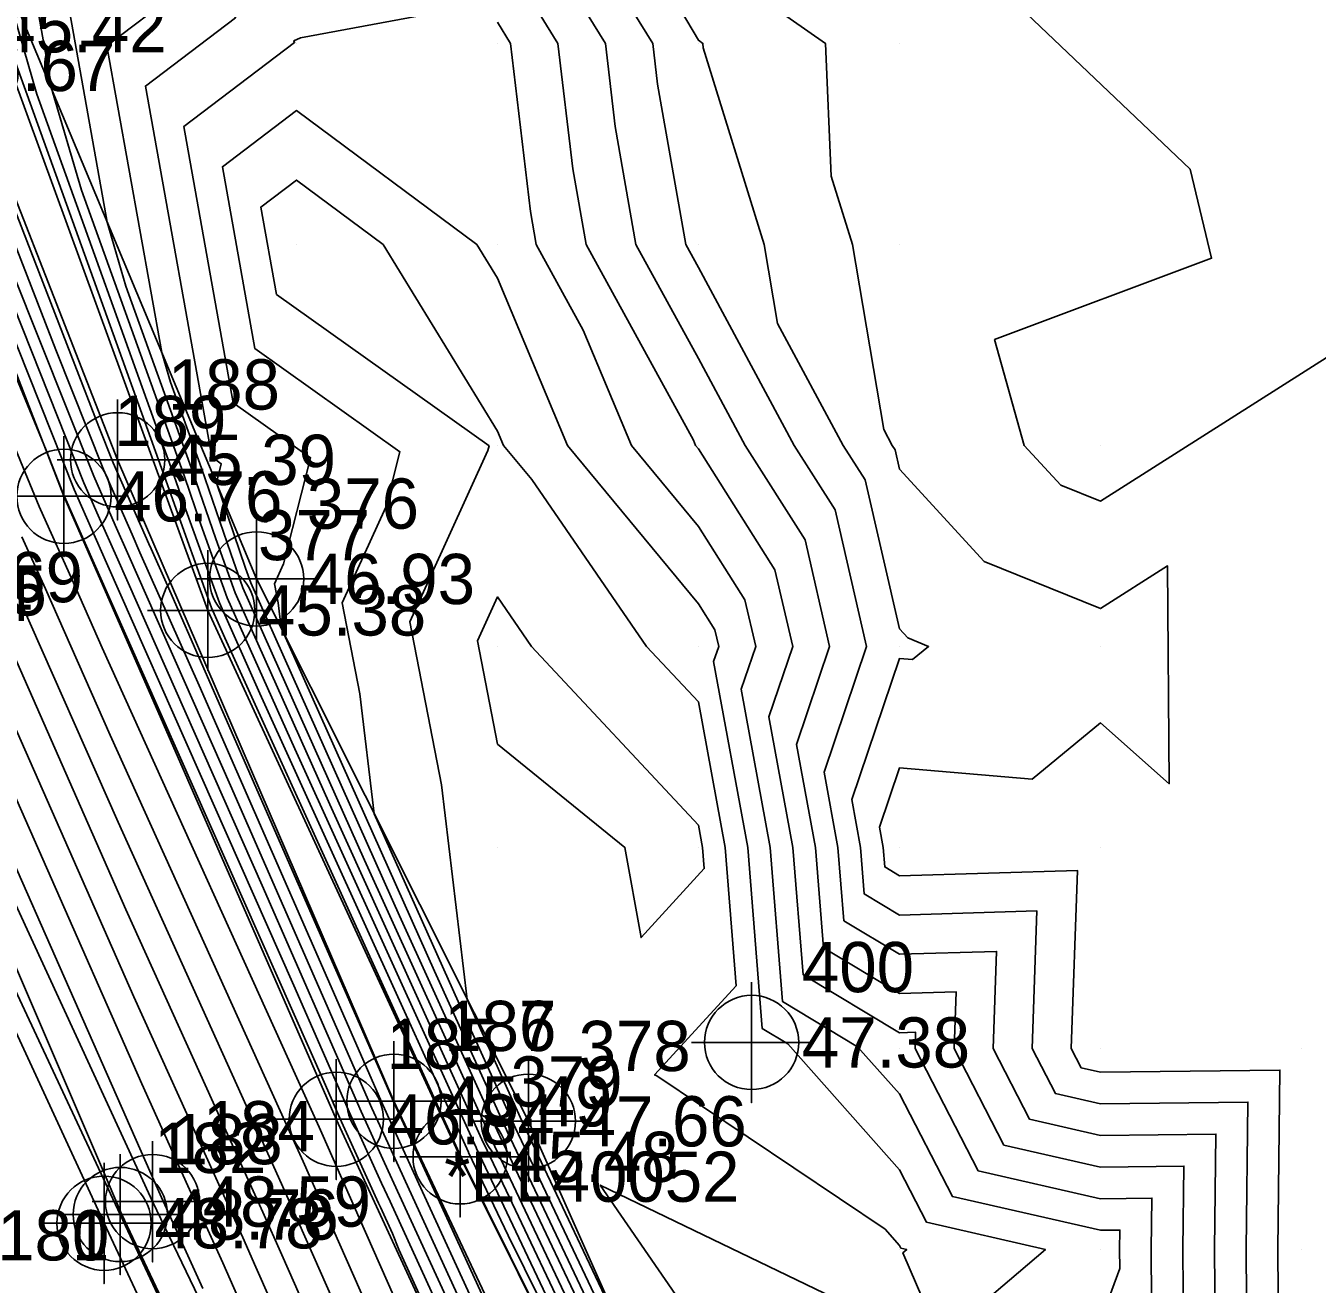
# Model space of a CAD drawing. Extents: x 2090860 to 2091277, y 159470 to 160080.
# Drawn here: x 2091106.5 to 2091170.8, y 159678.3 to 159740.9 of the extents above; entities that cross this region are included whole.
import ezdxf

# ---------------------------------------------------------------- set-up
doc = ezdxf.new("R2010")
doc.units = 0
for name, color, linetype in [('DTM Contours Major', 7, 'Continuous'), ('DTM Contours Minor', 7, 'Continuous'), ('Exist DTM Breakline', 7, 'Continuous'), ('Exist DTM Breakline Cogo Comment', 7, 'Continuous'), ('Exist DTM Breakline Cogo Elevation', 7, 'Continuous'), ('Exist DTM Breakline Cogo Number', 7, 'Continuous'), ('Exist DTM Breakline Cogo Point CELL', 7, 'Continuous'), ('Exist DTM Crownline Cogo Number', 7, 'Continuous'), ('Exist DTM QL2 LIDAR Elevation Point', 7, 'Continuous'), ('Exist DTM Regular Point CELL', 7, 'Continuous'), ('Exist DTM Regular Point Cogo Elevation', 7, 'Continuous'), ('Exist DTM Regular Point Cogo Number', 7, 'Continuous'), ('Exist Roads EOP', 7, 'Continuous'), ('Exist Roads EOP Cogo Elevation', 7, 'Continuous'), ('Exist Roads EOP Cogo Number', 7, 'Continuous'), ('Exist Roads EOP Cogo Point CELL', 7, 'Continuous'), ('Exist Roads EOT', 7, 'Continuous'), ('Exist Roads EOT Cogo Elevation', 7, 'Continuous'), ('Exist Roads EOT Cogo Number', 7, 'Continuous'), ('Exist Roads EOT Cogo Point CELL', 7, 'Continuous')]:
    doc.layers.add(name, color=color, linetype=linetype)

msp = doc.modelspace()

# ---------------------------------------------------------------- linework, layer by layer
at = {"layer": 'DTM Contours Major'}
for points in [[(2091113.978, 159781.196), (2091107.95, 159774.542), (2091109.45, 159770.226), (2091108.284, 159761.501), (2091106.966, 159748.316), (2091108.177, 159744.971), (2091106.747, 159743.886), (2091107.873, 159737.592), (2091109.304, 159732.696), (2091114.431, 159718.45), (2091115.247, 159716.067), (2091116.563, 159712.414), (2091119.92, 159704.896), (2091128.935, 159685.065), (2091128.953, 159685.024), (2091132.725, 159677.067), (2091142.133, 159658.086), (2091142.373, 159657.575), (2091143.105, 159656.097), (2091147.178, 159648.664), (2091157.027, 159629.517), (2091160.822, 159622.14), (2091162.224, 159619.585), (2091172.872, 159598.824)], [(2091167.296, 159672.704), (2091167.247, 159680), (2091167.328, 159687.328), (2091160, 159687.24), (2091157.753, 159687.753), (2091156.595, 159690), (2091156.838, 159696.838), (2091150, 159696.631), (2091148.246, 159697.686), (2091148.062, 159700), (2091147.627, 159702.373), (2091150, 159709.403), (2091150.652, 159709.348), (2091151.447, 159710), (2091150.417, 159710.417), (2091150, 159710.871), (2091148.285, 159718.285), (2091147.2, 159720), (2091143.935, 159726.065), (2091143.272, 159730), (2091140.232, 159739.768), (2091140.222, 159740), (2091140, 159740.155), (2091134.169, 159750)], [(2091126.87, 159693.834), (2091119.241, 159710.914), (2091119.091, 159712.158), (2091118.907, 159713.104), (2091119.361, 159714.098), (2091120.706, 159719.383), (2091116.861, 159722.121), (2091114.403, 159735.865), (2091119.906, 159740.039), (2091119.875, 159740.125), (2091120.209, 159740.28), (2091128.27, 159741.774)], [(2091130, 159741.057), (2091130.655, 159740), (2091131.642, 159731.642), (2091131.931, 159730), (2091134.269, 159725.731), (2091136.668, 159720), (2091140, 159715.97), (2091142.312, 159712.312), (2091142.847, 159710), (2091142.129, 159707.871), (2091143.571, 159700), (2091144.184, 159692.326), (2091147.91, 159690.084), (2091150, 159687.733), (2091152.629, 159682.629), (2091160, 159680.949), (2091160.96, 159680.96), (2091160.95, 159680), (2091160.956, 159679.044), (2091160, 159676.442)], [(2091133.499, 159658.093), (2091123.124, 159681.571), (2091121.327, 159685.637), (2091121.124, 159686.085), (2091110.337, 159709.925), (2091108.79, 159713.43), (2091107.412, 159716.477), (2091107.198, 159716.962), (2091099.863, 159734.767)], [(2091132.508, 159667.94), (2091125.612, 159682.971), (2091124.541, 159685.304), (2091123.76, 159687.025), (2091116.729, 159703.079), (2091111.667, 159714.499), (2091110.986, 159716.037), (2091109.918, 159718.472), (2091105.9, 159728.566)], [(2091121.742, 159670.624), (2091117.989, 159679.115), (2091117.339, 159680.586), (2091115.905, 159683.748), (2091111.915, 159692.566), (2091103.71, 159711.156)], [(2091172.606, 159609.793), (2091167.266, 159614.052), (2091165.877, 159617.077), (2091164.245, 159620.259), (2091159.237, 159629.383), (2091158.623, 159630.578), (2091157.028, 159633.678), (2091144.289, 159656.927), (2091144.155, 159657.198), (2091143.409, 159658.787), (2091141.517, 159662.605), (2091130.506, 159685.833), (2091130.452, 159685.953), (2091126.87, 159693.834)]]:
    msp.add_lwpolyline(points, dxfattribs=at)
at = {"layer": 'DTM Contours Minor'}
for points in [[(2091104.981, 159783.106), (2091105.494, 159775.383), (2091105.019, 159773.619), (2091104.746, 159770.703), (2091102.113, 159749.038), (2091103.646, 159746.449), (2091104.874, 159742.247), (2091113.588, 159718.033), (2091113.763, 159717.52), (2091115.783, 159711.911), (2091116.446, 159710.426), (2091128.176, 159684.621), (2091128.177, 159684.619), (2091128.329, 159684.298), (2091134.074, 159672.707)], [(2091113.452, 159782.082), (2091106.971, 159774.929), (2091107.612, 159773.082), (2091107.114, 159769.349), (2091104.896, 159747.166), (2091105.245, 159746.204), (2091104.833, 159745.892), (2091105.157, 159744.081), (2091107.089, 159737.471), (2091114.009, 159718.241), (2091114.505, 159716.794), (2091116.173, 159712.162), (2091118.183, 159707.661), (2091128.555, 159684.843), (2091128.565, 159684.821), (2091130.527, 159680.683), (2091141.814, 159657.91), (2091141.927, 159657.669), (2091142.809, 159655.89), (2091144.716, 159652.41), (2091156.628, 159629.252), (2091161.218, 159620.33), (2091161.719, 159619.417), (2091174.621, 159594.26)], [(2091122.861, 159781.908), (2091128.215, 159769.149), (2091125.426, 159758.204), (2091124.754, 159757.835), (2091125.475, 159756.447), (2091126.274, 159756.566), (2091136.123, 159756.123), (2091139.218, 159750), (2091140, 159748.68), (2091144.395, 159745.605), (2091153.611, 159744.078), (2091164.457, 159733.742), (2091165.521, 159729.312), (2091154.731, 159725.269), (2091156.202, 159720), (2091158.019, 159718.019), (2091160, 159717.218), (2091172.816, 159725.36)], [(2091122.375, 159778.639), (2091115.032, 159779.423), (2091109.908, 159773.768), (2091113.125, 159764.514), (2091111.434, 159751.856), (2091114.026, 159748.824), (2091112.082, 159747.918), (2091114.042, 159742.505), (2091110.575, 159739.876), (2091113.305, 159724.616), (2091113.735, 159723.145), (2091115.274, 159718.867), (2091116.731, 159714.614), (2091117.342, 159712.916), (2091123.395, 159699.365), (2091129.693, 159685.509), (2091129.729, 159685.429), (2091137.121, 159669.836)], [(2091122.253, 159777.822), (2091115.559, 159778.537), (2091110.888, 159773.381), (2091114.962, 159761.657), (2091114.117, 159755.328), (2091121.559, 159746.623), (2091115.979, 159744.021), (2091116.974, 159741.272), (2091112.489, 159737.87), (2091115.788, 159719.427), (2091116.265, 159719.088), (2091116.021, 159718.127), (2091117.473, 159713.888), (2091117.732, 159713.168), (2091125.132, 159696.599), (2091130.073, 159685.731), (2091130.118, 159685.631), (2091139.319, 159666.221)], [(2091164.126, 159675.874), (2091164.098, 159680), (2091164.144, 159684.144), (2091160, 159684.095), (2091155.191, 159685.191), (2091152.714, 159690), (2091152.814, 159692.814), (2091150, 159692.728), (2091146.215, 159695.006), (2091145.816, 159700), (2091144.878, 159705.122), (2091146.524, 159710), (2091145.299, 159715.299), (2091142.326, 159720), (2091140, 159724.32), (2091136.889, 159730), (2091135.859, 159735.859), (2091135.37, 159740), (2091130, 159748.673)], [(2091134.034, 159745.966), (2091137.728, 159740), (2091137.968, 159737.968), (2091139.368, 159730), (2091140, 159728.847), (2091144.763, 159720), (2091146.792, 159716.792), (2091148.363, 159710), (2091146.252, 159703.748), (2091146.939, 159700), (2091147.231, 159696.346), (2091150, 159694.68), (2091154.826, 159694.826), (2091154.655, 159690), (2091156.472, 159686.472), (2091160, 159685.668), (2091165.736, 159685.736), (2091165.673, 159680), (2091165.711, 159674.289)], [(2091162.541, 159677.459), (2091162.524, 159680), (2091162.552, 159682.552), (2091160, 159682.522), (2091153.91, 159683.91), (2091150.773, 159690), (2091150.802, 159690.802), (2091150, 159690.777), (2091145.2, 159693.666), (2091144.694, 159700), (2091143.503, 159706.497), (2091144.686, 159710), (2091143.806, 159713.806), (2091140, 159719.824), (2091139.855, 159720), (2091139.75, 159720.25), (2091134.41, 159730), (2091133.751, 159733.751), (2091133.012, 159740), (2091130, 159744.865)], [(2091168.882, 159671.118), (2091168.821, 159680), (2091168.92, 159688.92), (2091160, 159688.813), (2091159.034, 159689.034), (2091158.536, 159690), (2091158.85, 159698.85), (2091150, 159698.582), (2091149.262, 159699.026), (2091149.184, 159700), (2091149.001, 159700.999), (2091150, 159703.958), (2091156.6, 159703.4), (2091160, 159706.189), (2091163.416, 159703.168), (2091163.337, 159713.999), (2091160, 159711.879), (2091154.218, 159714.218), (2091150, 159718.818), (2091149.778, 159719.778), (2091149.637, 159720), (2091149.214, 159720.786), (2091147.664, 159730), (2091146.608, 159733.392), (2091146.313, 159740), (2091140, 159744.418)], [(2091113.443, 159677.236), (2091111.307, 159681.76), (2091110.309, 159684.106), (2091099.498, 159709.302), (2091098.524, 159711.61), (2091097.844, 159713.197), (2091091.534, 159728.707), (2091087.955, 159732.339), (2091087.995, 159731.685), (2091087.449, 159731.209), (2091080.082, 159737.993), (2091077.854, 159740.578), (2091075.81, 159742.572), (2091073.211, 159741.431)], [(2091134.923, 159673.452), (2091129.341, 159685.226), (2091129.314, 159685.287), (2091121.658, 159702.13), (2091116.952, 159712.665), (2091115.989, 159715.341), (2091114.853, 159718.658), (2091111.519, 159727.92), (2091110.589, 159731.104), (2091108.661, 159741.881)], [(2091135.085, 159663.655), (2091126.089, 159683.263), (2091124.693, 159686.307), (2091124.292, 159687.191), (2091115.156, 159708.052), (2091112.22, 159714.675), (2091111.825, 159715.567), (2091110.406, 159718.804), (2091108.04, 159724.748), (2091102, 159740.29)], [(2091137.663, 159659.37), (2091126.567, 159683.556), (2091124.845, 159687.31), (2091124.823, 159687.357), (2091113.582, 159713.024), (2091112.773, 159714.851), (2091112.664, 159715.097), (2091110.893, 159719.137), (2091110.18, 159720.929), (2091102.507, 159740.673)], [(2091134.42, 159659.528), (2091125.094, 159679.986), (2091124.774, 159680.795), (2091124.179, 159682.094), (2091124.086, 159682.295), (2091122.166, 159686.526), (2091121.45, 159688.161), (2091110.009, 159713.971), (2091108.468, 159717.447), (2091108.456, 159717.476), (2091107.547, 159719.758), (2091100.062, 159737.927)], [(2091128.607, 159691.069), (2091123.87, 159701.674), (2091123.152, 159707.632), (2091122.272, 159712.163), (2091124.445, 159716.918), (2091125.147, 159719.678), (2091117.935, 159724.816), (2091116.317, 159733.859), (2091120, 159736.653), (2091128.969, 159730), (2091130, 159728.317), (2091133.482, 159720), (2091140, 159712.115), (2091140.819, 159710.819), (2091141.009, 159710), (2091140.754, 159709.246), (2091142.449, 159700), (2091143.169, 159690.986), (2091144.437, 159690.223), (2091150, 159683.964), (2091151.348, 159681.348), (2091157.261, 159680), (2091153.346, 159676.654)], [(2091127.352, 159676.51), (2091124.656, 159682.386), (2091124.238, 159683.298), (2091122.697, 159686.693), (2091119.877, 159693.133), (2091110.562, 159714.147), (2091109.307, 159716.977), (2091108.943, 159717.808), (2091101.62, 159736.202)], [(2091130.344, 159688.303), (2091128.499, 159692.434), (2091127.213, 159703.107), (2091125.638, 159711.221), (2091129.528, 159719.738), (2091129.588, 159719.973), (2091119.008, 159727.51), (2091118.231, 159731.854), (2091120, 159733.196), (2091124.308, 159730), (2091130, 159720.706), (2091130.296, 159720), (2091131.706, 159718.294), (2091137.418, 159710), (2091140, 159707.236), (2091141.326, 159700), (2091141.876, 159693.116), (2091137.817, 159688.675), (2091137.929, 159688.629), (2091149.286, 159680.999), (2091150, 159680.196), (2091150.067, 159680.067), (2091150.359, 159680), (2091150.165, 159679.835), (2091154.402, 159670)], [(2091129.93, 159672.225), (2091125.134, 159682.678), (2091124.39, 159684.301), (2091123.229, 159686.859), (2091118.303, 159698.106), (2091111.115, 159714.323), (2091110.146, 159716.507), (2091109.431, 159718.14), (2091103.76, 159732.384)], [(2091130.56, 159661.226), (2091121.84, 159680.957), (2091120.33, 159684.374), (2091119.819, 159685.5), (2091110.732, 159705.585), (2091107.52, 159712.862), (2091106.348, 159715.454)], [(2091127.62, 159664.358), (2091120.556, 159680.343), (2091119.333, 159683.111), (2091118.515, 159684.916), (2091111.126, 159701.246), (2091106.25, 159712.293)], [(2091140.203, 159700), (2091140, 159701.11), (2091131.696, 159710), (2091130, 159712.463), (2091129.003, 159710.279), (2091130, 159705.141), (2091136.338, 159700), (2091137.149, 159695.51), (2091140.288, 159698.944), (2091140.203, 159700)], [(2091124.681, 159667.491), (2091119.273, 159679.729), (2091118.336, 159681.849), (2091117.21, 159684.332), (2091111.521, 159696.906), (2091104.98, 159711.725)], [(2091118.802, 159673.757), (2091116.705, 159678.502), (2091116.342, 159679.323), (2091114.601, 159683.164), (2091112.31, 159688.227), (2091102.441, 159710.588)], [(2091115.345, 159678.061), (2091113.296, 159682.58), (2091112.705, 159683.887), (2091101.171, 159710.019)], [(2091143.715, 159658.99), (2091130.894, 159686.036), (2091130.831, 159686.175), (2091128.607, 159691.069)], [(2091136.388, 159675.467), (2091131.282, 159686.238), (2091131.211, 159686.397), (2091130.344, 159688.303)], [(2091152.592, 159670), (2091150, 159676.016), (2091135.114, 159683.199), (2091147.379, 159665.386), (2091148.781, 159659.799), (2091148.987, 159659.463), (2091156.089, 159652.924), (2091151.579, 159660), (2091153.583, 159666.417), (2091152.592, 159670)]]:
    msp.add_lwpolyline(points, dxfattribs=at)
at = {"layer": 'Exist DTM Breakline'}
for points in [[(2091212.183, 159510.746), (2091191.689, 159549.546), (2091174.865, 159585.627), (2091158.431, 159619.302), (2091139.416, 159656.456), (2091124.853, 159687.366), (2091111.104, 159719.28), (2091102.676, 159740.8), (2091098.872, 159752.926), (2091092.871, 159757.669)], [(2091196.63, 159502.872), (2091177.33, 159544.144), (2091161.139, 159578.46), (2091145.393, 159612.39), (2091128.083, 159650.689), (2091112.842, 159682.377), (2091098.521, 159713.445), (2091088.424, 159738.261), (2091087.489, 159747.73)], [(2091104.06, 159746.702), (2091118.019, 159713.353), (2091131.537, 159686.371), (2091144.554, 159657.113), (2091164.611, 159620.381), (2091178.178, 159588.037), (2091195.659, 159551.391), (2091212.727, 159517.77)], [(2091103.084, 159746.105), (2091115.591, 159711.787), (2091128.144, 159684.602), (2091142.549, 159655.707), (2091161.438, 159619.323), (2091177.759, 159587.787), (2091194.782, 159551.104), (2091211.895, 159517.387)], [(2091206.488, 159507.898), (2091187.957, 159548.134), (2091170.754, 159583.555), (2091154.779, 159617.345), (2091136.615, 159654.772), (2091121.985, 159686.47), (2091108.438, 159717.464), (2091100.122, 159738.875)]]:
    msp.add_lwpolyline(points, dxfattribs=at)
at = {"layer": 'Exist DTM Breakline Cogo Point CELL'}
for points in [[(2091111.104, 159722.28), (2091111.104, 159716.28), (2091111.104, 159719.28), (2091114.104, 159719.28), (2091108.104, 159719.28)], [(2091108.438, 159720.464), (2091108.438, 159714.464), (2091108.438, 159717.464), (2091111.438, 159717.464), (2091105.438, 159717.464)], [(2091118.019, 159716.353), (2091118.019, 159710.353), (2091118.019, 159713.353), (2091121.019, 159713.353), (2091115.019, 159713.353)], [(2091115.591, 159714.787), (2091115.591, 159708.787), (2091115.591, 159711.787), (2091118.591, 159711.787), (2091112.591, 159711.787)], [(2091124.853, 159690.366), (2091124.853, 159684.366), (2091124.853, 159687.366), (2091127.853, 159687.366), (2091121.853, 159687.366)], [(2091124.853, 159690.366), (2091124.853, 159684.366), (2091124.853, 159687.366), (2091127.853, 159687.366), (2091121.853, 159687.366)], [(2091121.985, 159689.47), (2091121.985, 159683.47), (2091121.985, 159686.47), (2091124.985, 159686.47), (2091118.985, 159686.47)], [(2091131.537, 159689.371), (2091131.537, 159683.371), (2091131.537, 159686.371), (2091134.537, 159686.371), (2091128.537, 159686.371)], [(2091128.144, 159687.602), (2091128.144, 159681.602), (2091128.144, 159684.602), (2091131.144, 159684.602), (2091125.144, 159684.602)], [(2091112.842, 159685.377), (2091112.842, 159679.377), (2091112.842, 159682.377), (2091115.842, 159682.377), (2091109.842, 159682.377)]]:
    msp.add_lwpolyline(points, dxfattribs=at)
for centre in [(2091111.104, 159719.28), (2091108.438, 159717.464), (2091118.019, 159713.353), (2091115.591, 159711.787), (2091124.853, 159687.366), (2091124.853, 159687.366), (2091121.985, 159686.47), (2091131.537, 159686.371), (2091128.144, 159684.602), (2091112.842, 159682.377)]:
    msp.add_circle(centre, 2.344, dxfattribs=at)
at = {"layer": 'Exist DTM QL2 LIDAR Elevation Point'}
for p, q in [((2091120, 159740), (2091120, 159740)), ((2091130, 159740), (2091130, 159740)), ((2091140, 159740), (2091140, 159740)), ((2091150, 159740), (2091150, 159740)), ((2091120, 159730), (2091120, 159730)), ((2091130, 159730), (2091130, 159730)), ((2091140, 159730), (2091140, 159730)), ((2091150, 159730), (2091150, 159730)), ((2091130, 159720), (2091130, 159720)), ((2091140, 159720), (2091140, 159720)), ((2091150, 159720), (2091150, 159720)), ((2091160, 159720), (2091160, 159720)), ((2091130, 159710), (2091130, 159710)), ((2091140, 159710), (2091140, 159710)), ((2091150, 159710), (2091150, 159710)), ((2091160, 159710), (2091160, 159710)), ((2091130, 159700), (2091130, 159700)), ((2091140, 159700), (2091140, 159700)), ((2091150, 159700), (2091150, 159700)), ((2091160, 159700), (2091160, 159700)), ((2091150, 159690), (2091150, 159690)), ((2091160, 159690), (2091160, 159690)), ((2091170, 159690), (2091170, 159690)), ((2091150, 159680), (2091150, 159680)), ((2091160, 159680), (2091160, 159680)), ((2091170, 159680), (2091170, 159680))]:
    msp.add_line(p, q, dxfattribs=at)
at = {"layer": 'Exist DTM Regular Point CELL'}
msp.add_lwpolyline([(2091142.645, 159693.295), (2091142.645, 159687.295), (2091142.645, 159690.295), (2091145.645, 159690.295), (2091139.645, 159690.295)], dxfattribs=at)
msp.add_circle((2091142.645, 159690.295), 2.344, dxfattribs=at)
at = {"layer": 'Exist Roads EOP'}
msp.add_lwpolyline([(2091195.022, 159502.3), (2091175.816, 159543.301), (2091159.602, 159577.847), (2091143.942, 159611.542), (2091126.198, 159649.797), (2091111.241, 159681.734), (2091096.716, 159712.783), (2091082.116, 159745.373)], dxfattribs=at)
at = {"layer": 'Exist Roads EOP Cogo Point CELL'}
msp.add_lwpolyline([(2091111.241, 159684.734), (2091111.241, 159678.734), (2091111.241, 159681.734), (2091114.241, 159681.734), (2091108.241, 159681.734)], dxfattribs=at)
msp.add_circle((2091111.241, 159681.734), 2.344, dxfattribs=at)
at = {"layer": 'Exist Roads EOT'}
msp.add_lwpolyline([(2091194.37, 159502.018), (2091175.119, 159542.803), (2091158.987, 159577.703), (2091143.368, 159611.224), (2091125.349, 159649.375), (2091110.434, 159681.3), (2091096.012, 159712.514), (2091081.141, 159744.981)], dxfattribs=at)
at = {"layer": 'Exist Roads EOT Cogo Point CELL'}
msp.add_lwpolyline([(2091110.434, 159684.3), (2091110.434, 159678.3), (2091110.434, 159681.3), (2091107.434, 159681.3), (2091113.434, 159681.3)], dxfattribs=at)
msp.add_circle((2091110.434, 159681.3), 2.344, dxfattribs=at)

# ---------------------------------------------------------------- texts
at = {"layer": 'Exist DTM Breakline Cogo Comment'}
msp.add_text('*EL40052', height=2.5, dxfattribs=at).set_placement((2091127.353, 159682.366))
at = {"layer": 'Exist DTM Breakline Cogo Elevation'}
for s, p in [('45.42', (2091105.176, 159739.55)), ('46.67', (2091102.622, 159737.625)), ('45.39', (2091113.604, 159718.03)), ('46.76', (2091110.938, 159716.214)), ('48.69', (2091101.021, 159712.195)), ('46.93', (2091120.519, 159712.103)), ('45.38', (2091118.091, 159710.537)), ('45.49', (2091127.353, 159686.116)), ('45.49', (2091127.353, 159686.116)), ('46.84', (2091124.485, 159685.22)), ('47.66', (2091134.037, 159685.121)), ('45.48', (2091130.644, 159683.352)), ('48.59', (2091115.342, 159681.127))]:
    msp.add_text(s, height=2.5, dxfattribs=at).set_placement(p)
at = {"layer": 'Exist DTM Breakline Cogo Number'}
for s, p in [('188', (2091113.604, 159721.78)), ('189', (2091110.938, 159719.964)), ('376', (2091120.519, 159715.853)), ('377', (2091118.091, 159714.287)), ('187', (2091127.353, 159689.866)), ('186', (2091127.353, 159689.866)), ('185', (2091124.485, 159688.97)), ('378', (2091134.037, 159688.871)), ('379', (2091130.644, 159687.102)), ('184', (2091115.342, 159684.877))]:
    msp.add_text(s, height=2.5, dxfattribs=at).set_placement(p)
at = {"layer": 'Exist DTM Crownline Cogo Number'}
msp.add_text('181', height=2.5, dxfattribs=at).set_placement((2091105.114, 159679.449))
at = {"layer": 'Exist DTM Regular Point Cogo Elevation'}
msp.add_text('47.38', height=2.5, dxfattribs=at).set_placement((2091145.145, 159689.045))
at = {"layer": 'Exist DTM Regular Point Cogo Number'}
msp.add_text('400', height=2.5, dxfattribs=at).set_placement((2091145.145, 159692.795))
at = {"layer": 'Exist Roads EOP Cogo Elevation'}
for s, p in [('48.85', (2091099.216, 159711.533)), ('48.76', (2091113.741, 159680.484))]:
    msp.add_text(s, height=2.5, dxfattribs=at).set_placement(p)
at = {"layer": 'Exist Roads EOP Cogo Number'}
msp.add_text('183', height=2.5, dxfattribs=at).set_placement((2091113.741, 159684.234))
at = {"layer": 'Exist Roads EOT Cogo Elevation'}
for s, p in [('48.84', (2091098.512, 159711.264)), ('48.78', (2091112.934, 159680.05))]:
    msp.add_text(s, height=2.5, dxfattribs=at).set_placement(p)
at = {"layer": 'Exist Roads EOT Cogo Number'}
for s, p in [('182', (2091112.934, 159683.8)), ('180', (2091105.114, 159679.449))]:
    msp.add_text(s, height=2.5, dxfattribs=at).set_placement(p)

doc.saveas('drawing.dxf')
